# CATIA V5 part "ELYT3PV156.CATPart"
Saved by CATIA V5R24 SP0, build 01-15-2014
Part number: ELYT3PV156
Material "ZAMA": density 6700 kg/m3
Material "ZAMA": density 6700 kg/m3
Bounding box of the stored display mesh (mm): x -59 to 27.5, y 0 to 1560, z 0 to 1500
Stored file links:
  \\mnsrv021stg\Common\AREA TECNICA\Documenti\3D sito\Componenti risolti\ELYT3PV156.CATPart
  Z:\commesse\Novellini\Serie Zephiros\BH01S66\ID_18668_00.CATPart
  Z:\commesse\Novellini\Prove\Tabelladiprogetto1.txt
  Z:\commesse\Novellini\Prove\Tabelladiprogetto2.xls
  C:\Users\n.rebecchi\Desktop\Scambio\ID_35222_00.xls
  Z:\3D sito\BH02A.xlsx
  \\MNSRV021STG\Common\AREA TECNICA\Documenti\3D sito\BOX\ZEPHIROS\BH02A\BH02A.xls
  Z:\3D sito\ZEPHIROS\BH022P\BH022P.xls
  C:\Docisland\DocIsland\catia_workdir\diclient\N.REBECCHI\ID_21111_03.CATPart
  C:\Docisland\DocIsland\catia_workdir\diclient\N.REBECCHI\ID_29051_00.CATPart
  U:\AREA TECNICA\Documenti\3D sito\BOX\ZEPHYROS\ZEPHYR3P\BH013P.xls
  \\mnsrv021stg\Common\AREA TECNICA\Documenti\3D sito\BOX\ELYT\ZEPHYR3P\ELYT3PV.xls
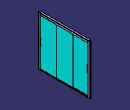
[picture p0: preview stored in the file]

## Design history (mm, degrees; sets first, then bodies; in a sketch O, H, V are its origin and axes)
Parameters
  `Larghezza anta` = 501 mm
  `MISURA NOMINALE` = 1560 mm
  PartNumber = "ELYT3PV156"
  `Lunghezza binario` = 1466 mm
Pad1: profile Sketch3.L13, length 1441, opposite side length -21
Solid1: solid without history
Solid2: solid without history
Pad2: profile Sketch3.L6, length 1441, opposite side length -21
Sketch1 on xy-plane, origin (0, 0, 0), H (1, 0, 0), V (0, 1, 0)
  axis line L1 (84.1025, 780) -> (-125.0839, 780)
  point P3 (-18.5, 0)
  point P4 (-18.5, 52.3)
  point P5 (0, 50.8)
  point P6 (-1.5, 52.3)
  point P8 (0, 1.5)
  point P9 (-1.5, 0)
  line L2 (0, 50.8) -> (0, 1.5)
  line L3 (-1.5, 0) -> (-32.75, 0)
  line L4 (-18.5, 1.5) -> (-18.5, 52.3)
  line L5 (-18.5, 52.3) -> (-1.5, 52.3)
  arc A1 centre (-1.5, 50.8) radius 1.5 from (0, 50.8) to (-1.5, 52.3) ccw
  arc A2 centre (-1.5, 1.5) radius 1.5 from (0, 1.5) to (-1.5, 0) cw
  line L6 (-18.5, 1.5) -> (-32.75, 1.5)
  point P11 (-32.75, 1.5)
  arc A3 centre (-32.75, 0.75) radius 0.75 from (-32.75, 1.5) to (-32.75, 0) ccw
  point P13 (-32.75, 0)
  point P14 (-18.5, 1.5)
  point P15 (-3, 1307.7)
  construction line L7 through (-1555.4, 0) direction (-1, 0)
  construction line L8 through (-1255.4, 0) direction (0, 1)
  point P16 (-18.5, 1560)
  point P17 (-18.5, 1507.7)
  point P18 (0, 1509.2)
  point P19 (-1.5, 1507.7)
  point P21 (0, 1558.5)
  point P22 (-1.5, 1560)
  point P24 (-32.75, 1558.5)
  point P26 (-32.75, 1560)
  point P27 (-18.5, 1558.5)
  line L9 (0, 1509.2) -> (0, 1558.5)
  line L10 (-1.5, 1560) -> (-32.75, 1560)
  line L11 (-18.5, 1558.5) -> (-18.5, 1509.1)
  line L12 (-52, 1507.7) -> (-1.5, 1507.7)
  arc A4 centre (-1.5, 1509.2) radius 1.5 from (0, 1509.2) to (-1.5, 1507.7) cw
  arc A5 centre (-1.5, 1558.5) radius 1.5 from (0, 1558.5) to (-1.5, 1560) ccw
  line L13 (-18.5, 1558.5) -> (-32.75, 1558.5)
  arc A6 centre (-32.75, 1559.25) radius 0.75 from (-32.75, 1558.5) to (-32.75, 1560) cw
  line L14 (-52, 1507.7) -> (-52, 1518.2)
  line L15 (-52, 1518.2) -> (-37, 1518.2)
  line L16 (-37, 1518.2) -> (-37, 1509.1)
  line L17 (-37, 1509.1) -> (-18.5, 1509.1)
  length L5 = 17
  radius A1 = 1.5
  distance L6 L3 = 1.5
  distance L4 A3 = 15
  distance L5 L3 = 52.3
  distance L2 L4 = 18.5
  radius A2 = 1.5
  distance L10 L3 = 1560 {= `MISURA NOMINALE`}
  distance L9 L14 = 52
  length L15 = 15
  distance L12 L17 = 1.4
  distance L15 L12 = 10.5
  tangency: A1 L2, A3 L3, A3 L6, L2 A2, A2 L3
  coincidence: P3 L3, P17 L11, P17 L12, L2 V, L3 L7, L3 H
  symmetry: P3 P16 L1, P4 P17 L1, P5 P18 L1, P6 P19 L1, P8 P21 L1, P9 P22 L1, P11 P24 L1, P13 P26 L1, P14 P27 L1, L2 L9 L1, L3 L10 L1, L4 L11 L1, L5 L12 L1, A1 A4 L1, A2 A5 L1, L6 L13 L1, A3 A6 L1
  vertical: L16 V
Pad3: profile Sketch1, direction (0, 0, 1), length 1500
Body1 "Telaio" (main body)
  Sketch2 on face of Pad3 from Sketch1.L5, origin (0, 52.3, 0), H (-1, 0, 0), V (0, 0, -1)
    point P1 (-1, -1500)
    line L1 (5.7859, -1500) -> (52.2221, -1500)
    line L2 (59, -1485.3692) -> (59, -1437.2118)
    construction line L3 (247.7599, -1440) -> (58, -1440)
    line L4 (-1, -1436.5) -> (-1, -1485.3692)
    point P2 (59, -1500)
    point P3 (59, -1440)
    construction line L5 (57.5, -1498) -> (57.5, -1486.5)
    construction line L6 (190.2599, -1498) -> (4.1139, -1498)
    point P5 (57.5, -1498)
    line L7 (57.7882, -1436) -> (-0.5, -1436)
    construction line L8 (8.597, -1485.5) -> (18.6226, -1485.5)
    construction line L9 (1.7786, -1486.5) -> (4.2562, -1486.5)
    construction line L10 (57.5, -1485.2) -> (57.5, -1440.5)
    construction line L11 (1, -1485) -> (1, -1464.277)
    point P6 (57.5, -1486.5)
    point P7 (1, -1485.5)
    construction line L12 (36.5779, -1495.9874) -> (36.5305, -1488.4874)
    construction line L13 (37.7781, -1496.0126) -> (37.7307, -1488.5126)
    construction line L14 (39.7307, -1486.5) -> (53.9552, -1486.5)
    construction line L15 (39.778, -1498) -> (50.7716, -1498)
    construction line L16 (18.9226, -1496) -> (18.9226, -1488.5)
    construction line L17 (20.1226, -1496) -> (20.1226, -1486.8)
    construction line L18 (20.4226, -1486.5) -> (34.5306, -1486.5)
    construction line L19 (22.1226, -1498) -> (34.5779, -1498)
    construction line L20 (18.9226, -1485.2) -> (18.9226, -1464.6071)
    construction line L21 (20.1226, -1485.2) -> (20.1226, -1466.4658)
    construction line L22 (36.5098, -1485.1981) -> (36.3815, -1464.8702)
    construction line L23 (37.7098, -1485.2019) -> (37.5963, -1467.2104)
    construction line L24 (20.4226, -1485.5) -> (222.4284, -1485.5)
    construction line L25 (38.0098, -1485.5) -> (57.2, -1485.5)
    construction line L26 (0.5, -1461.4168) -> (0.5, -1436.5)
    construction line L27 (46.4222, -1915.0185) -> (46.406, -1912.4534)
    construction line L28 (46.4222, -1915.0185) -> (47.9222, -1915.0091)
    construction arc A1 centre (8.7492, -1464.5115) radius 0.25 from (8.9992, -1464.5065) to (8.701, -1464.7568) cw
    construction arc A2 centre (5.7, -1465.25) radius 2.75 from (3.3803, -1463.773) to (8.3995, -1464.7254) cw
    point P12 (5.7, -1465.25)
    construction line L29 (1.4989, -1463.777) -> (3.3803, -1463.773)
    construction arc A3 centre (4.9238, -1464.5873) radius 4.0762 from (1.9856, -1461.762) to (9, -1464.5873) cw
    point P14 (8.9992, -1464.5065)
    construction arc A4 centre (8.7975, -1464.2662) radius 0.5 from (8.701, -1464.7568) to (8.321, -1464.4175) cw
    point P16 (8.321, -1464.4175)
    point P18 (23.1853, -1465.9683)
    point P19 (21.993, -1463.4903)
    point P20 (25.9312, -1465.8199)
    construction arc A5 centre (23.1853, -1465.9683) radius 2.75 from (21.993, -1463.4903) to (25.9123, -1465.6134) cw
    construction arc A6 centre (26.4305, -1465.7929) radius 0.5 from (25.9918, -1465.553) to (25.9312, -1465.8199) cw
    construction arc A7 centre (26.2112, -1465.6729) radius 0.25 from (26.45, -1465.7469) to (25.9918, -1465.553) cw
    construction arc A8 centre (23.4246, -1466.4658) radius 3.302 from (20.1226, -1466.4658) to (21.993, -1463.4903) cw
    point P24 (21.9929, -1463.4903)
    point P27 (40.6705, -1466.6867)
    construction arc A9 centre (43.6396, -1465.9948) radius 0.25 from (43.8765, -1466.0746) to (43.4818, -1466.1887) cw
    point P30 (43.3164, -1465.9372)
    construction arc A10 centre (43.7975, -1465.8009) radius 0.5 from (43.4818, -1466.1887) to (43.3164, -1465.9372) cw
    construction arc A11 centre (40.6705, -1466.6867) radius 2.75 from (39.5358, -1464.1817) to (43.3323, -1465.9959) cw
    construction arc A12 centre (40.8983, -1467.1895) radius 3.302 from (37.5963, -1467.2104) to (39.5358, -1464.1817) cw
    point P35 (211.7599, -1486.5)
    point P36 (12.6022, -1750.9456)
    point P37 (12.601, -1748.9456)
    point P38 (7.2208, -1496)
    point P39 (11.602, -1750.6462)
    point P40 (7.6073, -1494.5506)
    point P41 (7.6108, -1497.4484)
    point P42 (6.7699, -1497.6909)
    point P43 (5.9208, -1495.2516)
    point P44 (7.9723, -1497.2981)
    point P45 (5.9208, -1495.2516)
    point P46 (6.1845, -1494.2101)
    point P47 (7.9723, -1497.2981)
    point P48 (6.1845, -1494.2101)
    point P49 (6.7699, -1497.6909)
    point P50 (7.6073, -1494.5506)
    point P51 (7.6757, -1497.6898)
    point P52 (8.7353, -1495.1232)
    point P53 (5.9226, -1496.7516)
    point P54 (8.7353, -1495.1232)
    point P55 (5.9226, -1496.7516)
    point P56 (7.9692, -1494.7001)
    point P57 (7.9692, -1494.7001)
    point P58 (7.6108, -1497.4484)
    point P59 (7.6757, -1497.6898)
    construction arc A13 centre (7.2208, -1496) radius 1.5 from (7.6073, -1494.5506) to (7.6108, -1497.4484) ccw
    construction arc A14 centre (7.2208, -1496) radius 1.75 from (5.7042, -1495.1268) to (6.7699, -1497.6909) ccw
    construction line L30 (5.7042, -1495.1268) -> (5.9208, -1495.2516)
    construction arc A15 centre (7.2208, -1496) radius 1.5 from (7.9723, -1497.2981) to (5.9208, -1495.2516) ccw
    construction line L31 (6.1845, -1494.2101) -> (7.9723, -1497.2981)
    construction arc A16 centre (5.5354, -1494.5859) radius 0.75 from (6.1845, -1494.2101) to (5.5317, -1495.3359) ccw
    construction line L32 (6.7699, -1497.6909) -> (7.6073, -1494.5506)
    construction arc A17 centre (7.2208, -1496) radius 1.75 from (7.6757, -1497.6898) to (8.7353, -1495.1232) ccw
    construction line L33 (5.9226, -1496.7516) -> (8.7353, -1495.1232)
    construction arc A18 centre (7.2208, -1496) radius 1.5 from (5.9226, -1496.7516) to (7.9692, -1494.7001) ccw
    construction line L34 (7.9692, -1494.7001) -> (8.2527, -1494.2076)
    construction arc A19 centre (8.9027, -1494.5818) radius 0.75 from (9.4761, -1494.0984) to (8.2527, -1494.2076) ccw
    construction arc A20 centre (7.2208, -1496) radius 2.95 from (4.9609, -1494.1038) to (5.5608, -1493.5613) ccw
    construction line L35 (7.6108, -1497.4484) -> (7.6757, -1497.6898)
    point P60 (196.5645, -1917.6542)
    point P61 (11.6031, -1752.3962)
    point P62 (167.077, -1877.6984)
    construction line L36 (7.2208, -1496) -> (7.769, -1950.7895)
    point P63 (7.769, -1950.7895)
    construction line L37 (7.2208, -1496) -> (-0.9278, -1496)
    point P65 (4.9609, -1494.1038)
    point P67 (7.2232, -1498)
    construction line L38 (10.3276, -1498) -> (16.9226, -1498)
    construction arc A21 centre (4.1139, -1497.5) radius 0.5 from (4.5642, -1497.2826) to (4.1139, -1498) cw
    point P68 (4.5642, -1497.2826)
    construction arc A22 centre (7.2208, -1496) radius 2.95 from (9.4761, -1494.0984) to (9.8774, -1497.2826) cw
    construction arc A23 centre (10.3276, -1497.5) radius 0.5 from (9.8774, -1497.2826) to (10.3276, -1498) ccw
    point P74 (195.3181, -1910.0413)
    point P75 (197.3181, -1910.0413)
    point P77 (195.6181, -1911.0413)
    point P78 (193.8681, -1911.0413)
    point P79 (194.0428, -1910.0413)
    construction line L39 (198.7599, -1909.6171) -> (198.7599, -1904.8275)
    point P81 (196.7599, -1907.6171)
    construction line L40 (7.5212, -1762.7716) -> (7.5105, -1745.0224)
    point P85 (2.4259, -1750.9517)
    point P86 (2.4247, -1748.9517)
    point P88 (3.4257, -1750.6511)
    point P89 (3.4268, -1752.4011)
    point P90 (-151.896, -1877.8906)
    point P91 (7.5, -1950.7897)
    construction line L41 (7.5, -1935.9877) -> (7.5, -1950.7897)
    point P92 (7.5, -1497.9998)
    point P93 (2.4259, -1750.9517)
    point P94 (2.4247, -1748.9517)
    point P95 (7.5, -1487)
    point P96 (3.4257, -1750.6511)
    point P97 (7.8882, -1488.4489)
    point P98 (7.1118, -1488.4489)
    point P99 (7.9529, -1488.6904)
    point P100 (8.799, -1486.25)
    point P101 (8.25, -1485.701)
    point P102 (8.799, -1486.25)
    point P103 (8.5378, -1485.2025)
    point P104 (8.25, -1485.701)
    point P105 (8.5378, -1485.2025)
    point P106 (7.9529, -1488.6904)
    point P107 (7.8882, -1488.4489)
    point P108 (7.0471, -1488.6904)
    point P109 (5.9845, -1486.125)
    point P110 (6.201, -1486.25)
    point P111 (5.9845, -1486.125)
    point P112 (6.201, -1486.25)
    point P113 (6.75, -1485.701)
    point P114 (6.75, -1485.701)
    point P115 (7.1118, -1488.4489)
    point P116 (7.0471, -1488.6904)
    point P117 (3.4268, -1752.4011)
    point P118 (-151.896, -1877.8906)
    point P119 (7.5, -1950.7897)
    construction line L42 (7.5, -1487) -> (7.5, -1950.7897)
    point P120 (6.4659, -1485.2089)
    point P121 (7.5, -1497.9998)
    construction arc A24 centre (7.5, -1487) radius 1.5 from (7.8882, -1488.4489) to (7.1118, -1488.4489) cw
    construction arc A25 centre (7.5, -1487) radius 1.75 from (9.0155, -1486.125) to (7.9529, -1488.6904) cw
    construction line L43 (9.0155, -1486.125) -> (8.799, -1486.25)
    construction arc A26 centre (7.5, -1487) radius 1.5 from (8.25, -1485.701) to (8.799, -1486.25) cw
    construction line L44 (8.2506, -1485.7) -> (8.25, -1485.701)
    construction arc A27 centre (9.1873, -1485.5775) radius 0.75 from (8.5378, -1485.2025) to (9.6782, -1485.0105) cw
    construction line L45 (7.9529, -1488.6904) -> (7.8882, -1488.4489)
    construction arc A28 centre (7.5, -1487) radius 1.75 from (7.0471, -1488.6904) to (5.9845, -1486.125) cw
    construction line L46 (6.201, -1486.25) -> (5.9845, -1486.125)
    construction arc A29 centre (7.5, -1487) radius 1.5 from (6.201, -1486.25) to (6.75, -1485.701) cw
    construction line L47 (6.75, -1485.701) -> (6.7494, -1485.7)
    construction arc A30 centre (5.8164, -1485.5839) radius 0.75 from (5.2424, -1485.1011) to (6.4659, -1485.2089) cw
    construction arc A31 centre (7.5, -1487) radius 2.95 from (5.0963, -1485.2898) to (5.2424, -1485.1011) cw
    construction line L48 (7.1118, -1488.4489) -> (7.0471, -1488.6904)
    construction arc A32 centre (7.5, -1487) radius 2.95 from (4.5556, -1486.8185) to (10.45, -1487) ccw
    construction arc A33 centre (4.2562, -1486.8) radius 0.3 from (4.5556, -1486.8185) to (4.2562, -1486.5) ccw
    construction line L49 (16.9226, -1486.5) -> (10.95, -1486.5)
    construction arc A34 centre (10.95, -1487) radius 0.5 from (10.45, -1487) to (10.95, -1486.5) cw
    construction arc A35 centre (10.7882, -1483.9966) radius 1.5034 from (9.6782, -1485.0105) to (10.7882, -1485.5) ccw
    point P129 (9.6782, -1485.0105)
    point P130 (10.7882, -1485.5)
    construction line L50 (1.5, -1485.5) -> (6.403, -1485.5)
    construction arc A36 centre (4.6889, -1485) radius 0.5 from (5.0963, -1485.2898) to (4.6889, -1485.5) cw
    point P134 (4.6889, -1485.5)
    point P136 (9.6782, -1485.0105)
    construction arc A37 centre (6.403, -1485.9) radius 0.4 from (6.403, -1485.5) to (6.7494, -1485.7) cw
    construction arc A38 centre (8.597, -1485.9) radius 0.4 from (8.597, -1485.5) to (8.2506, -1485.7) ccw
    construction line L51 (191.961, -1463.0884) -> (240.5943, -1463.7586)
    construction line L52 (194.4697, -1470.2529) -> (261.0074, -1472.9865)
    construction circle A39 centre (7.2208, -1496) radius 1.75
    construction arc A40 centre (-0.5, -1499.5) radius 0.5 from (-1, -1499.5) to (-0.5, -1500) ccw
    point P147 (-1, -1499.5)
    point P148 (-0.5, -1500)
    construction arc A41 centre (58.5, -1499.5) radius 0.5 from (58.5, -1500) to (59, -1499.5) ccw
    point P150 (58.5, -1500)
    point P151 (59, -1499.5)
    arc A42 centre (-0.5, -1436.5) radius 0.5 from (-1, -1436.5) to (-0.5, -1436) cw
    construction arc A43 centre (0, -1436.5) radius 0.5 from (0, -1436) to (0.5, -1436.5) cw
    point P156 (0, -1436)
    construction arc A44 centre (58, -1440.5) radius 0.5 from (57.5, -1440.5) to (58, -1440) cw
    line L53 (-0.9205, -1485.76) -> (4.8654, -1499.3908)
    point P163 (-1, -1485.5727)
    arc A45 centre (5.7859, -1499) radius 1 from (4.8654, -1499.3908) to (5.7859, -1500) ccw
    point P164 (4.8654, -1499.3908)
    point P165 (5.7859, -1500)
    construction arc A46 centre (5.5292, -1495.8359) radius 0.5 from (5.5317, -1495.3359) to (5.0689, -1496.0313) cw
    construction arc A47 centre (1.7786, -1487) radius 0.5 from (1.3183, -1487.1954) to (1.7786, -1486.5) cw
    construction arc A48 centre (1.5, -1485) radius 0.5 from (1, -1485) to (1.5, -1485.5) ccw
    construction arc A49 centre (18.6226, -1485.2) radius 0.3 from (18.9226, -1485.2) to (18.6226, -1485.5) cw
    construction arc A50 centre (20.4226, -1485.2) radius 0.3 from (20.1226, -1485.2) to (20.4226, -1485.5) ccw
    construction arc A51 centre (16.9226, -1488.5) radius 2 from (16.9226, -1486.5) to (18.9226, -1488.5) cw
    construction line L54 (29, -1900.3555) -> (29, -1979.6079)
    point P187 (53.1346, -1499.3908)
    line L55 (58.9205, -1485.76) -> (53.1346, -1499.3908)
    arc A52 centre (52.2141, -1499) radius 1 from (53.1345, -1499.3908) to (52.2221, -1500) cw
    point P190 (59, -1485.5727)
    construction line L56 (55.7962, -1489.2815) -> (52.6126, -1496.7815)
    point P191 (-104.6902, -1867.3637)
    point P192 (-110.5556, -1881.1818)
    construction line L57 (59, -1485.5727) -> (-104.6902, -1867.3637)
    construction line L58 (53.1346, -1499.3908) -> (-110.5556, -1881.1818)
    construction line L59 (1.0011, -1461.9168) -> (1.6263, -1461.9155)
    construction arc A53 centre (1, -1461.4168) radius 0.5 from (0.5, -1461.4168) to (1.0011, -1461.9168) ccw
    construction arc A54 centre (1.6252, -1461.4155) radius 0.5 from (1.9856, -1461.762) to (1.6263, -1461.9155) cw
    construction arc A55 centre (22.7726, -1464.6071) radius 3.85 from (18.9226, -1464.6071) to (26.6226, -1464.6074) cw
    construction arc A56 centre (40.2297, -1464.8459) radius 3.8483 from (36.3815, -1464.8702) to (44.0779, -1464.8216) cw
    point P202 (40.2827, -1460.998)
    point P204 (43.8765, -1466.0746)
    point P205 (26.45, -1465.7469)
    arc A57 centre (0, -1485.3692) radius 1 from (-1, -1485.3692) to (-0.9205, -1485.76) ccw
    arc A58 centre (58, -1485.3692) radius 1 from (59, -1485.3692) to (58.9205, -1485.76) cw
    construction arc A59 centre (36.2098, -1485.2) radius 0.3 from (36.5098, -1485.1981) to (36.2098, -1485.5) cw
    construction arc A60 centre (38.0098, -1485.2) radius 0.3 from (37.7098, -1485.2019) to (38.0098, -1485.5) ccw
    construction arc A61 centre (39.7307, -1488.5) radius 2 from (37.7307, -1488.5126) to (39.7307, -1486.5) cw
    construction arc A62 centre (34.5306, -1488.5) radius 2 from (34.5306, -1486.5) to (36.5305, -1488.4874) cw
    construction arc A63 centre (34.5779, -1496) radius 2 from (36.5779, -1495.9874) to (34.5779, -1498) cw
    construction arc A64 centre (39.778, -1496) radius 2 from (37.7781, -1496.0126) to (39.778, -1498) ccw
    construction arc A65 centre (22.1226, -1496) radius 2 from (20.1226, -1496) to (22.1226, -1498) ccw
    construction arc A66 centre (16.9226, -1496) radius 2 from (18.9226, -1496) to (16.9226, -1498) cw
    construction arc A67 centre (50.7716, -1496) radius 2 from (52.6126, -1496.7815) to (50.7716, -1498) cw
    construction arc A68 centre (57.2, -1485.2) radius 0.3 from (57.5, -1485.2) to (57.2, -1485.5) cw
    construction arc A69 centre (1.5, -1464.277) radius 0.5 from (1, -1464.277) to (1.4989, -1463.777) cw
    construction arc A70 centre (53.9552, -1488.5) radius 2 from (53.9552, -1486.5) to (55.7962, -1489.2815) cw
    construction line L60 (1.3183, -1487.1954) -> (5.0689, -1496.0313)
    point P247 (162.3117, -1866.472)
    point P248 (168.0976, -1880.1028)
    construction line L61 (-0.9205, -1485.76) -> (162.3117, -1866.472)
    construction line L62 (4.8654, -1499.3908) -> (168.0976, -1880.1028)
    construction line L63 (57.3536, -1460.1464) -> (55.6464, -1461.8536)
    point P251 (57.5, -1460)
    construction line L64 (55.5, -1462.2071) -> (55.5, -1485)
    point P252 (55.5, -1485.5)
    construction arc A71 centre (55, -1485) radius 0.5 from (55.5, -1485) to (55, -1485.5) cw
    point P254 (55, -1485.5)
    construction arc A72 centre (56, -1462.2071) radius 0.5 from (55.5, -1462.2071) to (55.6464, -1461.8536) cw
    construction arc A73 centre (57, -1459.7929) radius 0.5 from (57.5, -1459.7929) to (57.3536, -1460.1464) cw
    point P259 (57.5, -1459.7929)
    construction line L65 (9, -1464.5873) -> (9, -1465.2632)
    construction arc A74 centre (8.7, -1465.2632) radius 0.3 from (9, -1465.2632) to (8.4, -1465.2632) cw
    construction line L66 (8.3995, -1464.7254) -> (8.4, -1465.2632)
    axis line L67 (204.6582, -1469.5884) -> (238.7986, -1470.2896)
    construction line L68 (26.6226, -1464.6074) -> (26.6225, -1465.5674)
    construction arc A75 centre (26.2659, -1465.5674) radius 0.3566 from (25.9123, -1465.6134) to (26.6225, -1465.5674) ccw
    construction line L69 (44.0779, -1464.8216) -> (44.0847, -1465.8974)
    construction arc A76 centre (43.7024, -1465.8999) radius 0.3823 from (43.3323, -1465.9959) to (44.0847, -1465.8974) ccw
    point P279 (213.6284, -1912.5175)
    point P280 (222.8519, -1905.6947)
    point P281 (220.8519, -1903.6947)
    point P282 (222.4284, -1485.5)
    point P283 (222.4284, -1485.5)
    construction line L70 (222.4284, -1485.5) -> (36.2098, -1485.5)
    construction arc A77 centre (20.4226, -1486.8) radius 0.3 from (20.1226, -1486.8) to (20.4226, -1486.5) cw
    arc A78 centre (57.7882, -1437.2118) radius 1.2118 from (57.7882, -1436) to (59, -1437.2118) cw
    point P290 (0, 0)
    point P291 (0, 0)
    point P304 (0.6, -33)
    line L71 (0.5, 0) -> (48.5, 0)
    line L72 (50, -1.5) -> (50, -11.2929)
    line L73 (0, -17.5) -> (48.1743, -13.2853)
    line L74 (-0.5, -35) -> (0.0954, -35)
    line L75 (-1, -34.5) -> (-1, -1.5)
    arc A79 centre (0.5, -1.5) radius 1.5 from (-1, -1.5) to (0.5, 0) cw
    line L76 (0, -32.0835) -> (0, -17.5)
    arc A80 centre (-0.5, -34.5) radius 0.5 from (-1, -34.5) to (-0.5, -35) ccw
    arc A81 centre (48, -11.2929) radius 2 from (48.1743, -13.2853) to (50, -11.2929) ccw
    line L77 (0.6, -34.4954) -> (0.6, -33)
    arc A82 centre (0.0954, -34.4954) radius 0.5046 from (0.0954, -35) to (0.6, -34.4954) ccw
    arc A83 centre (0.1, -33) radius 0.5 from (0.3, -32.5417) to (0.6, -33) cw
    arc A84 centre (0.5, -32.0835) radius 0.5 from (0.3, -32.5417) to (0, -32.0835) cw
    arc A85 centre (48.5, -1.5) radius 1.5 from (50, -1.5) to (48.5, 0) ccw
    reference intersected line E1 through (0, 0) direction (0, -1) from face of Pad3 from Sketch1.L2
    reference intersected line E2 (18.5, -1500) -> (1.5, -1500) from end face of Pad3
    point P312 (0, -17.5)
    distance L2 L5 = 1.5
    distance L1 L6 = 2
    distance L8 L9 = 1
    distance L20 L21 = 1.2
    distance L22 L23 = 1.2
    distance L11 L20 = 17.9226 (reference)
    distance L23 L27 = 6
    radius A1 = 0.25
    radius A2 = 2.75
    distance L11 P12 = 4.7 (reference)
    radius A4 = 0.5
    radius A7 = 0.25
    radius A6 = 0.5
    radius A5 = 2.75
    radius A11 = 2.75
    radius A9 = 0.25
    radius A10 = 0.5
    radius A14 = 1.75
    distance A14 A15 = 0.25
    radius A13 = 1.5
    radius A20 = 2.95
    angle L31 L36 = 330
    angle L34 L31 = 60
    angle L30 L31 = 30
    angle L32 L35 = 30
    angle L35 L33 = 105
    radius A19 = 0.75
    radius A16 = 0.75
    angle L34 L33 = 30
    angle L31 L30 = 30 (reference)
    radius A21 = 0.5
    radius A23 = 0.5
    distance P38 P95 = 9
    radius A33 = 0.3
    radius A34 = 0.5
    radius A35 = 1.5034
    radius A28 = 1.75
    radius A32 = 2.95
    radius A29 = 1.5
    radius A36 = 0.5
    angle L47 L44 = 60
    radius A30 = 0.75
    angle L44 L43 = 30
    radius A27 = 0.75
    angle L42 L48 = 15
    radius A37 = 0.4
    radius A38 = 0.4
    distance P12 L50 = 20.25
    distance L29 P12 = 1.482
    distance A3 L29 = 3.2585
    distance L29 A1 = 1
    distance P18 P27 = 17.5
    radius A12 = 3.302
    radius A8 = 3.302
    radius A3 = 4.0762
    distance A3 P12 V = 3.4134 (reference)
    distance P18 P12 = 17.5
    distance L1 P38 = 4
    radius A40 = 0.5
    distance P2 P3 = 60
    radius A41 = 0.5
    radius A42 = 0.5
    radius A43 = 0.5
    radius A44 = 0.5
    distance L4 P95 = 8.5
    radius A45 = 1
    angle L53 L4 = 157
    distance L4 P165 = 6.7859
    distance P163 L1 = 14.4273 (reference)
    radius A46 = 0.5
    radius A47 = 0.5
    radius A48 = 0.5
    distance L22 P27 = 4.2774
    radius A49 = 0.3
    radius A50 = 0.3
    radius A51 = 2
    distance L4 L26 = 1.5
    length L4 = 48.8692 (reference)
    distance L55 L56 = 1.5
    radius A53 = 0.5
    radius A54 = 0.5
    distance L29 L59 = 1.8612
    distance L11 L4 = 2
    distance L20 A55 = 7.7
    radius A9 = 0.25 (reference)
    distance L22 L69 = 7.6965
    radius A57 = 1
    radius A58 = 1
    radius A59 = 0.3
    radius A60 = 0.3
    radius A61 = 2
    radius A62 = 2
    radius A63 = 2
    radius A64 = 2
    radius A65 = 2
    radius A66 = 2
    radius A67 = 2
    radius A68 = 0.3
    radius A69 = 0.5
    radius A70 = 2
    distance L53 L60 = 1.5
    distance L16 L17 = 1.2 (reference)
    distance L20 L16 = 0
    distance L21 L17 = 0
    distance L22 L12 = 0
    distance L13 L23 = 0
    distance L12 L13 = 1.2 (reference)
    distance L1 L25 = 14.5
    distance P251 L3 = 20
    distance L2 L64 = 3.5
    angle L63 L10 = 135
    radius A71 = 0.5
    radius A72 = 0.5
    radius A73 = 0.5
    radius A74 = 0.3
    distance A74 L51 = 5
    distance L11 L65 = 8 (reference)
    radius A75 = 0.3566 (reference)
    radius A76 = 0.3823 (reference)
    distance L20 L65 = 9.9226
    distance L65 P12 = 3.3
    distance L4 P12 = 6.7
    distance L1 L7 = 64
    radius A77 = 0.3
    radius A78 = 1.2118
    distance L1 H = 1500 (reference)
    distance L71 L74 = 35
    distance L75 E1 = 1
    distance L75 L72 = 51
    distance L75 L76 = 1
    radius A85 = 1.5
    radius A81 = 2
    radius A80 = 0.5
    radius A82 = 0.5046
    distance L75 L77 = 1.6
    radius A83 = 0.5
    radius A84 = 0.5
    radius A79 = 1.5
    distance L2 L4 = 60
    angle L71 L73 = 5
    distance L71 P312 = 17.5
    distance L74 P304 = 2
    coincidence: L5 L10, L9 L14, L6 L15, L9 L18, L6 L19, L8 L24, L24 L25, A8 P24, P24 A5, A8 P19, P19 A5, A14 A17, A13 A15, A18 A13, L34 P38, L31 P38, P47 P44, P43 P45, P59 P51, P49 P42, L32 P38, L35 P38, L33 P38, P53 P55, P54 P52, P57 P56, P48 P46, L30 P38, P41 P58, P40 L32, L6 L38, L36 P67, L6 P67, L38 P67, P102 P100, P104 P101, P105 P103, P106 P99, P107 P97, P111 P109, P112 P110, P114 P113, P115 P98, P116 P108, L9 P35, L8 P7, A28 A25, A26 A24, A29 A26, P129 A31, P136 P129, A31 A32, L44 P95, L43 P95, L48 P95, L50 P134, L47 P120, L8 P130, L44 P103, L8 L50, L4 P1, L1 P1, L1 P2, L2 P2, L3 P3, L2 P3, P147 L4, P148 L1, A20 P68, A16 P65, L11 P7, L50 P7, L49 P35, P150 L1, P151 L2, P192 L56, P5 L15, P191 L56, P6 L14, A56 P202, P202 L51, L4 P163, L53 P163, L2 P190, L55 P190, L60 P62, P247 L60, P248 L60, P251 L10, P252 L25, P251 L63, L64 P252, P14 A3, P16 A2, A5 P20, P205 A55, A11 P30, P204 A56, P259 L10, P254 L25, L24 P282, L24 L70, P283 P282, L7 P156, P50 P40, L71 H, L4 L75, L1 E2
    tangency: A3 A1, A4 A1, A2 A4, A5 A6, A6 A7, A11 A10, A10 A9, A19 L34, A16 L31, A19 A20, A16 A20, A21 L6, A21 A20, A22 A16, A23 A22, A23 L38, A33 A32, A33 L9, L49 A33, A34 A32, A34 L49, A35 A31, A35 L8, L50 A24, A36 A31, A36 L50, L44 A27, L47 A30, A31 A30, A37 L50, A37 L47, A38 L8, A38 L44, L51 A3, L52 A2, L52 A5, A11 L52, A8 A5, A11 A12, A8 L21, A12 L23, A40 L4, A40 L1, A41 L1, A41 L2, A42 L4, A42 L7, A43 L7, A43 L26, A44 L10, A44 L3, A45 L53, A45 L1, A46 A16, A47 L9, A48 L11, A48 L50, A49 L20, A49 L8, A50 L21, A50 L24, A51 L49, A51 L16, A53 L26, A53 L59, A54 L59, A54 A3, A55 L51, L20 A55, A55 A7, A56 L22, A56 L51, A9 A56, A57 L4, A57 L53, A58 L2, A58 L55, A59 L22, A59 L24, A60 L23, A60 L25, A61 L13, A61 L14, A62 L18, A62 L12, A63 L12, A63 L19, A64 L13, A64 L15, A65 L17, A65 L19, A66 L16, A66 L38, A67 L56, A67 L15, A68 L10, A68 L25, A69 L11, A69 L29, A70 L14, A70 L56, A47 L60, A46 L60, A71 L64, A71 L25, A72 L64, A72 L63, A73 L10, A73 L63, L65 A3, L66 A74, L65 A74, L67 A74, A7 L67, L68 A55, A75 L68, A75 A5, A75 L67, L69 A56, A76 L69, A76 A11, L67 A76, A77 L17, A77 L18, A78 L7, A78 L2, L71 A85, L72 A85, L72 A81, A81 L73, A84 L76, L77 A83, L71 A79, L75 A79, A83 A84
    concentricity: A17 A14, A14 P38, P38 A39, A20 A14, A32 A28, A28 P95, A26 A24, A29 A28
    symmetry: P36 P85 L40, P37 P86 L40, P39 P88 L40, P61 P89 L40, P62 P90 L40, P63 P91 L40, L36 L41 L40, P67 P92 L40, P36 P93 L40, P37 P94 L40, P39 P96 L40, P61 P117 L40, P62 P118 L40, P63 P119 L40, L36 L42 L40, P67 P121 L40, L47 L44 L42, L46 L43 L42, L48 L45 L42, L4 L2 L54, P164 P187 L54, L53 L55 L54, A45 A52 L54
  Pad4: profile Sketch2, direction (0, 1, 0), up to face of Pad3 from Sketch1.L12
Body2 "Maniglia sx"
Body3 "Vetro sx"
Body4 "maniglia dx"
Body5 "Vetro centrale"
  Pad5: profile Sketch3.L2, length 1441, opposite side length -21
  Sketch3 on xy-plane, origin (0, 0, 0), H (1, 0, 0), V (0, 1, 0)
    point P1 (-22, 627.7)
    line L1 (-19.0001, 529.0303) -> (-25, 528.9985)
    line L2 (-25, 528.9985) -> (-25, 1029.9985)
    line L3 (-25, 1029.9985) -> (-19, 1029.9978)
    line L4 (-19, 1029.9978) -> (-19, 529.0303)
    point P6 (-39.5, 1257.2002)
    line L5 (-36.5, 1006.7) -> (-42.5, 1006.7008)
    line L6 (-42.5, 1006.7008) -> (-42.5, 1507.7)
    line L7 (-42.5, 1507.7) -> (-36.5, 1507.7)
    line L8 (-36.5, 1507.7) -> (-36.5, 1006.7)
    construction line L9 (-39.5, 1257.2002) -> (-39.5, -213.0288)
    point P12 (-4.5, 301.9137)
    line L10 (-1.5, 51.4234) -> (-7.5, 51.4235)
    line L11 (-7.5, 51.4235) -> (-7.5, 552.3916)
    line L12 (-7.5, 552.3916) -> (-1.5, 552.4234)
    line L13 (-1.5, 552.4234) -> (-1.5, 51.4234)
    construction line L14 (-4.5, 301.9137) -> (-122.8046, 301.9137)
    point P18 (4, -1)
    point P19 (4, 1038.4)
    axis line L15 (-22, 627.7) -> (-154.4866, 627.7)
    reference projected line E1 (-1.5, 1507.7) -> (-48.1743, 1507.7) from edge [face of Pad3 from Sketch1.L12 | face of Pad4 from Sketch2.L73]
    length L2 = 501 {= `Larghezza anta`}
    length L8 = 501 {= `Larghezza anta`}
    length L1 = 6
    length L5 = 6
    length L10 = 6
    length L13 = 501 {= `Larghezza anta`}
    distance L13 L4 = 17.5
    distance L8 L4 = 17.5
    distance L3 L5 = 23.3
    distance L12 L1 = 23.3
    distance L13 V = 1.5
    distance L11 L13 = 6
    distance L4 L2 = 6
    distance L6 L8 = 6
    distance L7 E1 = 0
    equidistance: L2 L4 P1, L5 L7 P6, L6 L8 P6, L10 L12 P12, L11 L13 P12
    vertical: L9 V
Body6 "Vetro dx"
Relations
  Value = `Larghezza anta`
